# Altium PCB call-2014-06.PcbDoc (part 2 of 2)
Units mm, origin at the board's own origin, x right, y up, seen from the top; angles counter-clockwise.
Board outline 60 x 92 mm, 2 copper layers (Top Layer, Bottom Layer); 65 components, 45 nets, 265 pads, 33 vias.
Unrouted connection lines stored in the file: 4.
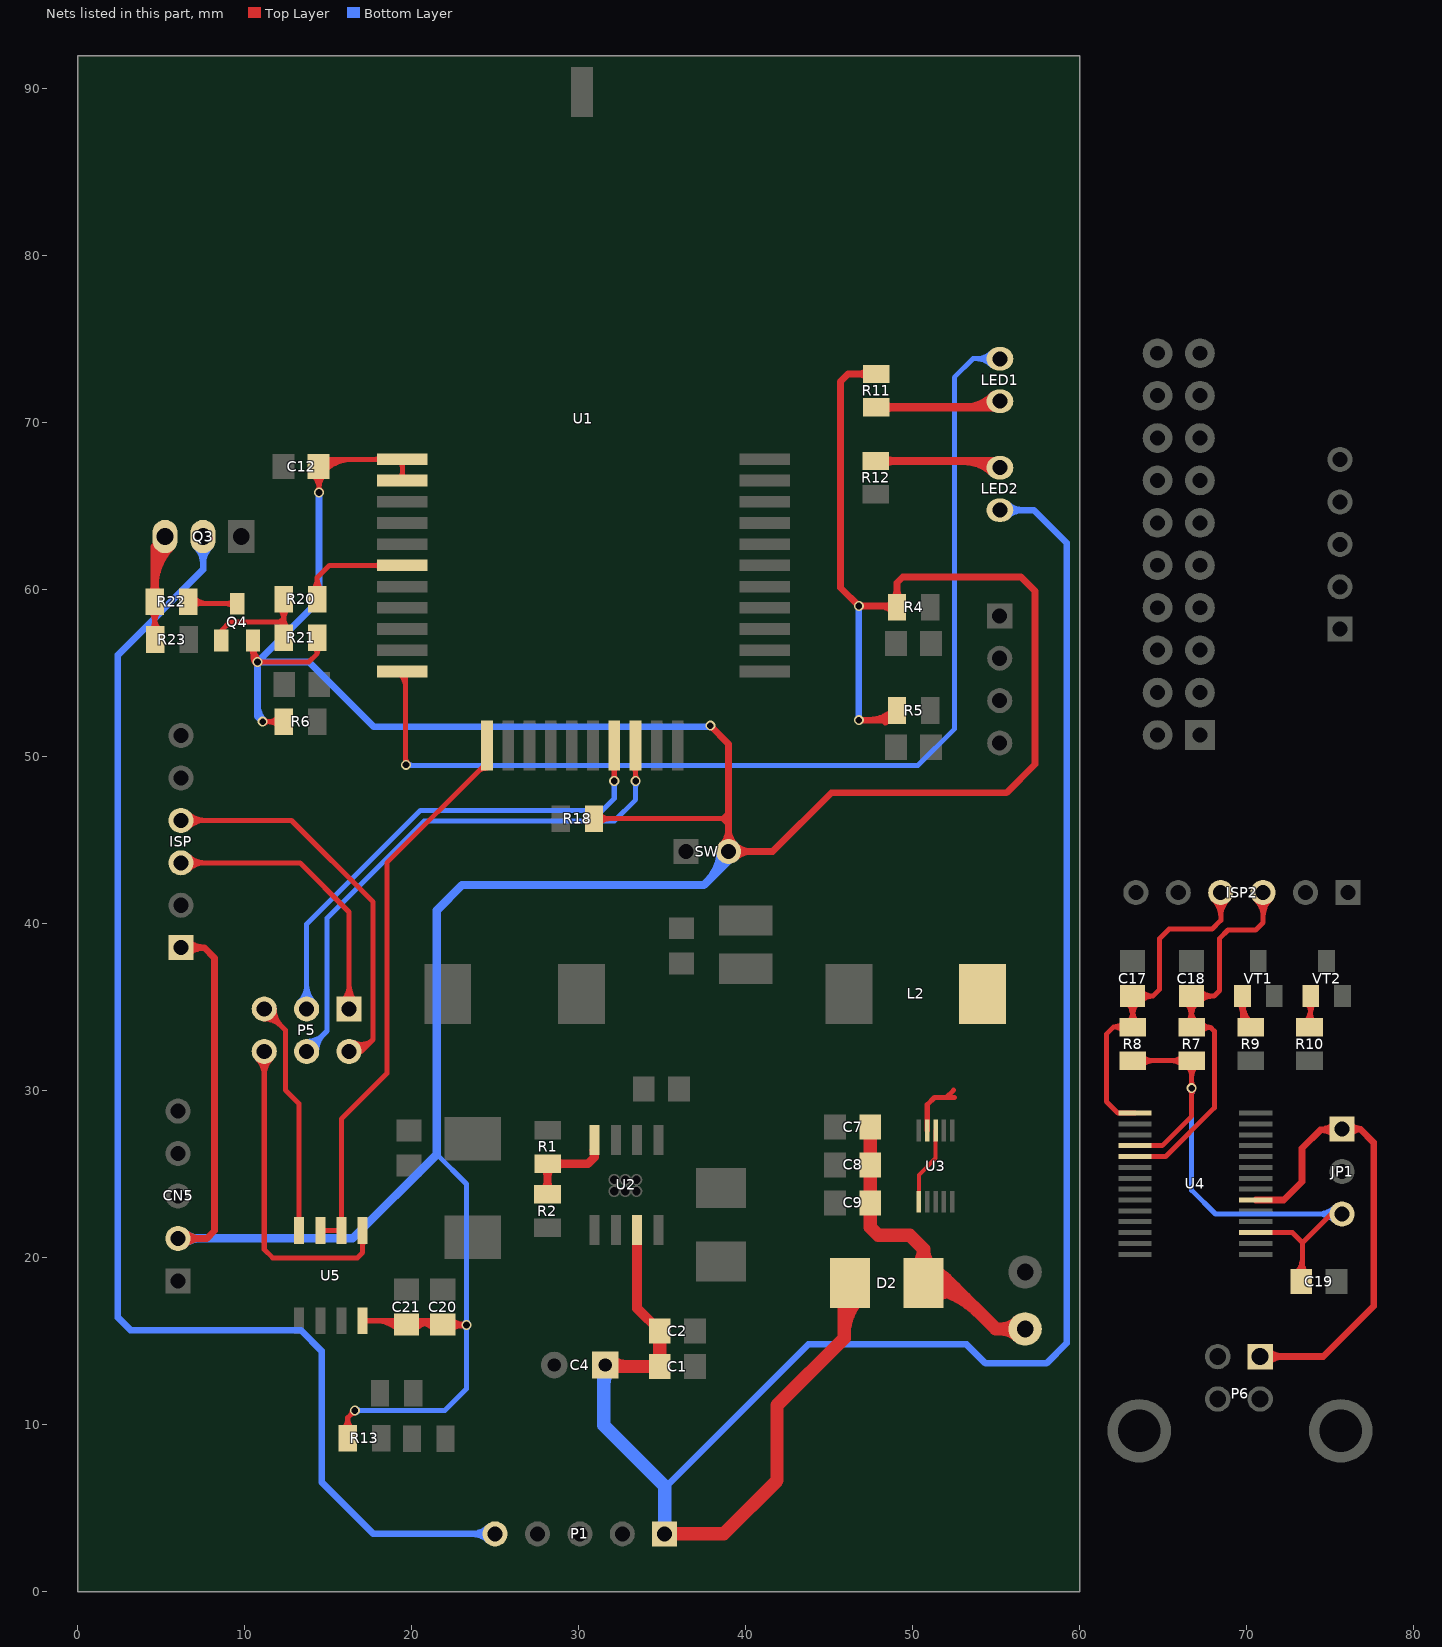
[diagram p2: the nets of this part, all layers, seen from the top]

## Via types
v1: diameter 0.6, hole 0.4, Top Layer to Bottom Layer, 33 vias

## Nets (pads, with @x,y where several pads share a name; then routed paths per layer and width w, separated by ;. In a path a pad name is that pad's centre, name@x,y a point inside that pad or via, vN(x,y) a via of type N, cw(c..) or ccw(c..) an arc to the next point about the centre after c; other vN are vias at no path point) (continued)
NetL2_1: L2.1 U3.9 | length 4
  Top Layer w0.3: U3.9@50.88,27.635 50.88,29.177 51.315,29.612 52.515,29.612 ; 52.024,29.614 52.459,30.049
NetLED1_1: LED1.1 R11.2 | length 11.4
  Top Layer w0.5: R11.2@47.82,70.93 54.86,70.93 LED1.1@55.23,71.3 ; R11.2@48.282,70.718 cw(c48.794,70.206) 48.794,70.93 cw(c48.794,71.654) R11.2@48.282,71.142 ; 53.15,70.93 ccw(c53.15,73.28) LED1.1@54.812,71.618 ; 54.357,70.93 ccw(c54.357,72.073) LED1.1@55.165,71.265
NetLED2_2: LED2.2 R12.2 | length 11.6
  Top Layer w0.5: R12.2@47.79,67.72 54.83,67.72 LED2.2@55.23,67.32 ; R12.2@48.252,67.508 cw(c48.764,66.996) 48.764,67.72 cw(c48.764,68.444) R12.2@48.252,67.932 ; 53.078,67.72 cw(c53.078,65.268) LED2.2@54.812,67.002 ; 54.285,67.72 cw(c54.285,66.475) LED2.2@55.165,67.355
NetQ3_3: Q3.3 R22.1 R23.2 | length 14.9
  Top Layer w0.3: R22.1@4.337,58.757 cw(c3.654,58.074) 4.62,58.074 cw(c5.586,58.074) R22.1@4.903,58.757 ; R23.2@4.367,57.563 ccw(c3.757,58.173) 4.62,58.173 ; 4.62,58.318 ccw(c5.688,58.318) R23.2@4.933,57.563 ; R22.1@4.62,59.29 4.62,57.06 R23.2@4.65,57.03
  Top Layer w0.5: R22.1@4.408,59.752 ccw(c3.896,60.264) 4.62,60.264 ccw(c5.344,60.264) R22.1@4.832,59.752 ; R22.1@4.62,59.29 4.62,62.579 Q3.3@5.24,63.199 ; 4.62,60.245 cw(c7.944,60.245) Q3.3@5.594,62.595 ; 4.62,61.452 cw(c6.737,61.452) Q3.3@5.24,62.949
NetQ4_1: Q4.1 R20.1 R21.1 | length 10
  Top Layer w0.3: Q4.1@8.611,56.975 8.611,57.552 9.134,58.075 12.126,58.075 12.351,58.3 ; R21.1@12.068,57.663 ccw(c11.385,58.346) 12.351,58.346 ccw(c13.317,58.346) R21.1@12.634,57.663 ; R20.1@12.068,58.917 cw(c11.385,58.234) 12.351,58.234 cw(c13.317,58.234) R20.1@12.634,58.917 ; R21.1@12.351,57.13 R20.1@12.351,59.45
NetQ4_3: Q4.3 R22.2 | length 5.5
  Top Layer w0.3: R22.2@6.62,59.29 6.735,59.175 Q4.3@9.561,59.175 ; R22.2@6.903,59.007 cw(c7.308,58.602) 7.308,59.175 ; R22.2@6.903,59.573 ccw(c7.863,60.533) 7.863,59.175 ; Q4.3@9.367,58.981 ccw(c8.897,58.511) 8.897,59.175 ccw(c8.897,59.839) Q4.3@9.367,59.369
NetR1_1: R1.1 R2.1 U2.4 | length 9.9
  Top Layer w0.5: R2.1@27.928,24.022 ccw(c27.416,24.534) 28.14,24.534 ccw(c28.864,24.534) R2.1@28.352,24.022 ; R1.1@27.938,25.438 cw(c27.45,24.95) 28.14,24.95 ; R2.1@28.14,23.81 R1.1@28.14,25.64 ; 28.14,24.902 cw(c28.898,24.902) R1.1@28.362,25.438 ; R1.1@28.15,25.65 R1.1@28.14,25.64 ; R1.1@28.612,25.438 cw(c29.1,24.95) 29.1,25.64 ; R1.1@28.612,25.862 ccw(c29.148,26.398) 29.148,25.64 ; 30.787,25.857 ccw(c30.385,26.259) U2.4@30.919,26.453 ; U2.4@30.966,27.07 30.966,26.036 30.57,25.64 R1.1@28.14,25.64
NetR9_1: R9.1 VT1.1 | length 5.8
  Top Layer w0.3: VT1.1@69.505,35.283 cw(c68.908,34.685) 69.753,34.685 cw(c70.598,34.685) VT1.1@70,35.283 ; 69.753,34.632 ccw(c70.816,34.632) R9.1@70.064,33.881 ; VT1.1@69.753,35.357 ccw(c71.54,35.357) R9.1@70.276,34.093 ; VT1.1@69.753,35.68 69.753,33.817 R9.1@70.03,33.54
NetR10_1: R10.1 VT2.1 | length 4.7
  Top Layer w0.3: R10.1@73.487,34.093 ccw(c72.635,34.945) 73.84,34.945 ; VT2.1@73.593,35.283 cw(c72.995,34.685) 73.84,34.685 cw(c74.685,34.685) VT2.1@74.087,35.283 ; 73.84,34.607 ccw(c74.567,34.607) R10.1@74.053,34.093 ; VT2.1@73.84,35.68 73.84,34.06 R10.1@74.01,33.89
NetR20_2: R20.2 U1.6 | length 9
  Top Layer w0.3: R20.2@14.068,59.983 ccw(c13.38,60.671) 14.353,60.671 ; R20.2@14.351,59.45 14.353,59.452 14.353,60.741 15.082,61.47 U1.6@19.446,61.47 ; 14.353,60.661 ccw(c15.312,60.661) R20.2@14.634,59.983 ; U1.6@18.155,61.329 ccw(c17.813,60.987) 17.813,61.47 ccw(c17.813,61.953) U1.6@18.155,61.611
PA1: LED1.2 U1.11 | length 67
  Top Layer w0.3: U1.11@19.305,54.979 cw(c18.5,54.174) 19.638,54.174 ; U1.11@19.446,55.12 19.638,54.928 v1@19.638,49.526 ; 19.638,49.97 ccw(c20.116,49.97) v1@19.778,49.632
  Bottom Layer w0.3: v1@19.718,49.495 50.33,49.495 52.499,51.664 52.499,72.729 53.622,73.852 LED1.2@54.899,73.852 ; v1@19.778,49.632 ccw(c20.109,49.963) 20.109,49.495 ; 53.773,73.852 cw(c53.773,72.483) LED1.2@54.741,73.451 ; 53.831,73.852 ccw(c53.831,75.139) LED1.2@54.741,74.229
  other v1: 19.672,49.526
RW: P1.5 Q3.2 | length 85.6
  Bottom Layer w0.4: Q3.2@7.131,62.56 cw(c6.192,61.621) 7.52,61.621 cw(c8.848,61.621) Q3.2@7.909,62.56 ; Q3.2@7.52,63.199 7.52,61.216 2.412,56.108 2.412,16.432 3.165,15.679 13.364,15.679 14.619,14.424 14.619,6.581 17.72,3.48 P1.5@25,3.48 ; P1.5@24.611,3.091 ccw(c23.672,2.152) 23.672,3.48 ccw(c23.672,4.808) P1.5@24.611,3.869
SHINENG: U1.12 U5.2 U5.3 | length 36.2
  Top Layer w0.3: U5.3@14.536,21.64 U5.2@15.806,21.64 15.806,28.326 18.52,31.04 18.52,43.658 24.518,49.656 U1.12@24.518,50.683 ; U5.3@14.642,21.534 cw(c14.898,21.278) 14.898,21.64 cw(c14.898,22.002) U5.3@14.642,21.746 ; U5.2@15.7,21.534 ccw(c15.444,21.278) 15.444,21.64 ccw(c15.444,22.002) U5.2@15.7,21.746 ; U5.2@15.7,22.246 ccw(c15.444,22.502) 15.806,22.502 ccw(c16.168,22.502) U5.2@15.912,22.246 ; 23.967,49.105 cw(c24.518,48.553) U1.12@24.518,49.333
UART_RXD: P5.5 U1.19 | length 37.3
  Top Layer w0.3: U1.19@33.267,49.392 cw(c32.9,49.025) 33.419,49.025 ; v1@33.312,48.665 ccw(c33.056,48.921) 33.419,48.921 ccw(c33.781,48.921) v1@33.525,48.665 ; U1.19@33.408,50.683 33.419,50.673 v1(33.419,48.559) ; 33.419,49.076 cw(c33.865,49.076) U1.19@33.549,49.392
  Bottom Layer w0.3: P5.5@13.72,32.37 14.941,33.591 14.941,40.349 20.753,46.161 32.142,46.161 33.419,47.437 v1(33.419,48.559) ; P5.5@13.72,32.97 ccw(c13.72,34.419) 14.744,33.394 ccw(c15.769,32.37) P5.5@14.32,32.37 ; v1@33.312,48.453 cw(c33.056,48.197) 33.419,48.197 cw(c33.781,48.197) v1@33.525,48.453
"UART_RXD 485": P5.6 U5.1 | length 22.3
  Top Layer w0.3: P5.6@10.756,31.946 cw(c9.731,30.921) 11.18,30.921 cw(c12.629,30.921) P5.6@11.604,31.946 ; P5.6@11.18,32.37 11.18,20.512 11.682,20.01 16.76,20.01 17.076,20.326 U5.1@17.076,21.64 ; U5.1@16.97,21.034 cw(c16.714,20.778) 17.076,20.778 cw(c17.438,20.778) U5.1@17.182,21.034
UART_RXD_USB: C18.2 ISP2.3 ISP.3 P5.1 R7.1 U4.5 | length 54.1
  Top Layer w0.3: ISP.3@6.19,43.66 13.32,43.66 16.26,40.72 P5.1@16.26,34.91 ; ISP.3@6.614,43.236 cw(c7.639,42.211) 7.639,43.66 cw(c7.639,45.109) ISP.3@6.614,44.084 ; P5.1@15.836,35.334 ccw(c14.811,36.359) 16.26,36.359 ccw(c17.709,36.359) P5.1@16.684,35.334 ; U4.5@63.32,26.07 65.155,26.07 68.07,28.985 68.07,33.58 67.84,33.81 ; C18.2@66.344,35.326 cw(c65.49,34.473) 66.697,34.473 cw(c67.904,34.473) C18.2@67.051,35.326 ; R7.1@66.434,34.093 ccw(c65.798,34.729) 66.697,34.729 ; 66.697,34.822 ccw(c67.729,34.822) R7.1@67,34.093 ; C18.2@67.151,35.326 cw(c68.004,34.473) 68.004,35.68 cw(c68.004,36.887) C18.2@67.151,36.034 ; R7.1@67.27,33.549 cw(c67.84,33.057) 67.84,33.81 ; R7.1@67.27,34.071 ccw(c67.84,34.563) 67.84,33.81 ; ISP2.3@70.566,41.456 cw(c69.541,40.431) 70.99,40.431 cw(c72.439,40.431) ISP2.3@71.414,41.456 ; ISP2.3@70.99,41.88 70.99,40.08 70.55,39.64 68.89,39.64 68.39,39.14 68.39,36.02 68.05,35.68 C18.2@66.697,35.68 66.697,33.829 R7.1@66.717,33.81 67.84,33.81
UART_TXD: P5.2 U1.18 | length 34
  Top Layer w0.3: U1.18@31.997,49.392 cw(c31.655,49.05) 32.138,49.05 cw(c32.621,49.05) U1.18@32.279,49.392 ; v1@32.032,48.665 ccw(c31.776,48.921) 32.138,48.921 ccw(c32.5,48.921) v1@32.244,48.665 ; v1(32.138,48.559) U1.18@32.138,50.683
  Bottom Layer w0.3: P5.2@13.296,35.334 ccw(c12.271,36.359) 13.72,36.359 ccw(c15.169,36.359) P5.2@14.144,35.334 ; P5.2@13.72,34.91 13.72,39.993 20.524,46.797 31.423,46.797 32.138,47.512 v1(32.138,48.559) ; v1@32.032,48.453 cw(c31.776,48.197) 32.138,48.197 cw(c32.5,48.197) v1@32.244,48.453
"UART_TXD 485": P5.3 U5.4 | length 17
  Top Layer w0.3: P5.3@11.18,34.31 cw(c11.18,32.861) 12.204,33.886 cw(c13.229,34.91) P5.3@11.78,34.91 ; P5.3@11.18,34.91 12.45,33.64 12.45,30.05 13.266,29.234 U5.4@13.266,21.64 ; U5.4@13.16,22.246 ccw(c12.904,22.502) 13.266,22.502 ccw(c13.628,22.502) U5.4@13.372,22.246
UART_TXD_USB: C17.2 ISP2.4 ISP.4 P5.4 R8.1 U4.1 | length 58.3
  Top Layer w0.3: ISP.4@6.19,46.2 12.81,46.2 17.7,41.31 17.7,33.08 ; ISP.4@6.614,45.776 cw(c7.639,44.751) 7.639,46.2 cw(c7.639,47.649) ISP.4@6.614,46.624 ; P5.4@15.99,32.35 16.97,32.35 17.7,33.08 ; P5.4@16.26,32.37 ccw(c16.601,33.023) 17.122,32.502 ; P5.4@16.399,32.636 ccw(c16.799,33.403) 17.411,32.791 ; P5.4@16.538,32.902 ccw(c16.998,33.782) 17.7,33.08 ; 62.047,33.84 ccw(c62.047,34.703) R8.1@62.657,34.093 ; R8.1@62.629,33.559 ccw(c62.04,33.083) 62.04,33.84 ; C17.2@62.826,35.326 cw(c61.973,34.473) 63.18,34.473 cw(c64.387,34.473) C17.2@63.534,35.326 ; R8.1@62.907,34.093 ccw(c62.248,34.752) 63.18,34.752 ; R8.1@63.18,33.82 C17.2@63.18,35.68 64.39,35.68 ; 63.18,34.8 ccw(c64.18,34.8) R8.1@63.473,34.093 ; R8.1@63.19,33.81 63.16,33.84 62.04,33.84 ; U4.1@63.32,28.67 62.3,28.67 61.6,29.37 61.6,33.4 62.04,33.84 ; C17.2@63.654,35.349 cw(c64.39,34.698) 64.39,35.68 ; C17.2@63.654,36.011 ccw(c64.39,36.662) 64.39,35.68 ; ISP2.4@68.026,41.456 cw(c66.977,40.407) 68.46,40.407 ; ISP2.4@68.45,41.88 68.46,41.87 68.46,40.22 67.93,39.69 65.36,39.69 64.8,39.13 64.8,36.09 64.39,35.68 ; 68.46,40.456 cw(c69.874,40.456) ISP2.4@68.874,41.456
VCC: JP1.1 P6.1 U4.20 | length 33.8
  Top Layer w0.4: U4.20@70.559,23.47 72.23,23.47 73.32,24.56 73.32,26.57 74.42,27.67 ; P6.1@70.815,14.095 74.595,14.095 77.61,17.11 77.61,26.92 76.82,27.71 ; P6.1@71.212,13.697 cw(c72.173,12.736) 72.173,14.095 cw(c72.173,15.453) P6.1@71.212,14.492 ; 74.489,27.67 cw(c74.489,26.479) JP1.1@75.331,27.321 ; JP1.1@75.306,28.072 cw(c74.42,28.847) 74.42,27.67 ; JP1.1@76.16,27.38 cw(c76.82,26.885) 76.82,27.71 ; JP1.1@76.16,28.04 ccw(c76.82,28.535) 76.82,27.71 ; 74.42,27.67 75.68,27.67 JP1.1@75.72,27.71 76.82,27.71
VCC_9V: C7.2 C8.2 C9.2 D2.1 pad.0@56.74,15.75 U3.1 U3.8 | length 42.9
  Top Layer w0.254: U3.1@50.38,23.36 50.38,24.973 51.38,25.973 U3.8@51.38,27.635
  Top Layer w0.8: C7.2@47.51,28.102 47.464,28.056 47.464,21.832 47.946,21.35 49.83,21.35 50.66,20.52 ; D2.1@50.121,18.781 cw(c51.029,17.785) 51.982,18.738 ; D2.1@50.142,19.4 ccw(c49.19,20.52) 50.66,20.52 ; D2.1@50.66,18.99 cw(c50.66,16.404) 52.488,18.233 ; D2.1@51.178,19.4 cw(c52.13,20.52) 50.66,20.52 ; D2.1@51.199,17.599 cw(c52.16,16.548) 53.166,17.555 ; D2.1@51.307,18.019 cw(c52.231,17.348) 52.231,18.49 ; D2.1@51.307,18.961 ccw(c52.231,19.632) 52.231,18.49 ; 52.574,18.147 ccw(c51.594,17.167) 50.66,18.19 cw(c50.66,13.673) 53.854,16.867 ; pad.0@56.316,15.326 ccw(c55.291,14.301) 55.291,15.75 ccw(c55.291,17.199) pad.0@56.316,16.174 ; pad.0@56.74,15.75 54.971,15.75 52.231,18.49 ; 50.66,20.52 D2.1@50.66,18.49 52.231,18.49
VCC_24V: C1.2 C2.2 C4.1 D2.2 LED2.1 P1.1 U2.7 | length 135.8
  Top Layer w0.6: U2.7@33.506,21.67 33.506,16.984 C2.2@34.87,15.62
  Top Layer w0.8: C4.1@31.594,13.59 31.684,13.5 C1.2@34.87,13.5 ; C4.1@31.877,13.873 ccw(c32.777,14.773) 32.777,13.5 ; C1.2@34.78,13.59 C1.2@34.87,13.5 ; C2.2@34.95,15.84 34.87,15.76 C1.2@34.87,13.5 ; P1.1@35.16,3.48 38.695,3.48 41.886,6.671 41.886,11.174 45.9,15.188 D2.2@45.9,18.45 ; P1.1@35.407,3.233 cw(c36.005,2.635) 36.005,3.48 cw(c36.005,4.325) P1.1@35.407,3.727 ; 45.9,15.39 cw(c49.06,15.39) D2.2@46.826,17.624
  Bottom Layer w0.4: 35.16,6.229 43.757,14.826 53.239,14.826 54.378,13.687 58.01,13.687 59.23,14.907 59.23,62.809 57.259,64.78 LED2.1@55.23,64.78 ; LED2.1@55.684,64.426 cw(c56.537,63.573) 56.537,64.78 cw(c56.537,65.987) LED2.1@55.684,65.134
  Bottom Layer w0.8: 31.519,12.443 cw(c32.741,12.443) C4.1@31.877,13.307 ; C4.1@31.594,13.59 31.519,13.515 31.519,9.975 35.16,6.334 ; P1.1@34.913,3.727 ccw(c34.315,4.325) 35.16,4.325 ccw(c36.005,4.325) P1.1@35.407,3.727 ; P1.1@35.16,3.48 35.16,6.229
VDD33: C12.2 C19.2 C20.2 C21.2 CN5.2 ISP.1 JP1.3 Q4.2 R4.2 R5.2 R6.2 R7.2 R8.2 R11.1 R13.2 R18.2 R21.2 SW.2 U1.1 U1.2 U4.4 U4.17 U5.8 | length 346.4
  Top Layer w0.3: Q4.2@10.317,56.556 cw(c9.879,56.118) 10.498,56.118 ; 10.498,55.991 ccw(c11.085,55.991) v1@10.67,55.576 ; 10.498,56.055 cw(c11.206,56.055) Q4.2@10.705,56.556 ; Q4.2@10.498,56.715 ccw(c11.809,56.715) 10.882,55.788 ccw(c11.138,56.044) 11.138,55.682 ccw(c11.138,55.32) v1@10.882,55.576 ; Q4.2@10.511,56.975 10.498,56.962 10.498,55.96 v1(10.776,55.682) 13.85,55.682 14.351,56.183 ; v1(11.087,52.116) R6.2@12.351,52.116 ; v1@11.193,52.01 cw(c11.449,51.754) 11.449,52.116 cw(c11.449,52.478) v1@11.193,52.222 ; R6.2@12.068,51.833 ccw(c11.385,51.15) 11.385,52.116 ccw(c11.385,53.082) R6.2@12.068,52.399 ; C12.2@14.08,66.927 cw(c13.159,66.006) v1@14.462,66.006 ; R21.2@14.149,56.535 cw(c13.944,56.183) 14.351,56.183 ; R21.2@14.351,57.13 14.351,56.183 ; v1@14.356,65.943 ccw(c14.1,66.199) 14.462,66.199 ccw(c14.824,66.199) v1@14.568,65.943 ; C12.2@14.363,67.552 cw(c15.011,66.904) C12.2@15.011,67.82 ; C12.2@14.434,67.381 C12.2@14.462,67.353 ; v1(14.462,65.837) C12.2@14.462,67.353 ; 14.462,66.141 cw(c15.574,66.141) C12.2@14.788,66.927 ; R21.2@14.553,56.535 ccw(c14.758,56.183) 14.351,56.183 ; C12.2@14.575,67.34 cw(c15.735,66.18) 15.735,67.82 ; C12.2@14.788,67.127 cw(c16.46,65.455) 16.46,67.82 ; R13.2@15.897,9.733 ccw(c15.214,10.416) 16.18,10.416 ccw(c17.146,10.416) R13.2@16.463,9.733 ; R13.2@16.18,9.2 16.18,10.439 v1(16.604,10.863) ; v1@16.454,10.863 cw(c16.092,10.863) 16.348,10.607 cw(c16.604,10.351) v1@16.604,10.713 ; U5.8@17.076,16.24 21.64,16.24 C20.2@21.87,16.01 ; U5.8@17.182,16.134 cw(c17.438,15.878) 17.438,16.24 cw(c17.438,16.602) U5.8@17.182,16.346 ; 17.828,16.24 cw(c17.828,14.248) C21.2@19.236,15.656 ; U1.1@18.155,67.679 ccw(c17.813,67.337) 17.813,67.82 ccw(c17.813,68.303) U1.1@18.155,67.961 ; 18.552,16.24 cw(c18.552,14.972) C21.2@19.449,15.869 ; 18.938,16.24 ccw(c18.938,16.662) C21.2@19.236,16.364 ; U1.2@19.305,66.691 ccw(c18.963,67.033) 19.446,67.033 ccw(c19.929,67.033) U1.2@19.587,66.691 ; U1.1@19.305,67.679 cw(c18.963,67.337) 19.446,67.337 cw(c19.929,67.337) U1.1@19.587,67.679 ; U1.2@19.446,66.55 U1.1@19.446,67.82 14.929,67.82 C12.2@14.462,67.353 ; C21.2@19.931,15.869 cw(c20.828,14.972) 20.828,16.24 ; C21.2@20.008,16.24 cw(c20.008,14.248) C20.2@21.416,15.656 ; C21.2@20.144,15.656 cw(c21.552,14.248) C20.2@21.552,16.24 ; C21.2@20.144,16.364 ccw(c20.442,16.662) 20.442,16.24 ; 20.732,16.24 cw(c20.732,14.972) C20.2@21.629,15.869 ; 21.118,16.24 ccw(c21.118,16.662) C20.2@21.416,16.364 ; R18.2@30.841,46.52 R18.2@31.138,46.817 ; R18.2@30.925,46.304 38.624,46.304 ; R18.2@31.208,46.021 cw(c31.891,45.338) 31.891,46.304 cw(c31.891,47.27) R18.2@31.208,46.587 ; 38.984,45.944 38.624,46.304 ; 38.984,46.664 38.624,46.304 ; R8.2@63.19,31.81 R7.2@66.717,31.81 66.717,28.487 64.95,26.72 U4.4@63.32,26.72 ; R8.2@63.723,31.527 cw(c64.406,30.844) 64.406,31.81 cw(c64.406,32.776) R8.2@63.723,32.093 ; R7.2@66.184,31.527 ccw(c65.501,30.844) 65.501,31.81 ccw(c65.501,32.776) R7.2@66.184,32.093 ; R7.2@66.434,31.527 cw(c65.751,30.844) 66.717,30.844 cw(c67.682,30.844) R7.2@67,31.527 ; v1@66.611,30.064 cw(c66.355,29.808) 66.717,29.808 cw(c67.079,29.808) v1@66.823,30.064 ; v1@66.611,30.276 ccw(c66.355,30.532) 66.717,30.532 ccw(c67.079,30.532) v1@66.823,30.276 ; U4.17@70.559,21.52 72.74,21.52 73.35,20.91 ; C19.2@72.926,19.034 ccw(c71.904,20.056) 73.35,20.056 ; C19.2@73.139,18.821 ccw(c72.628,19.332) 73.35,19.332 ; C19.2@73.28,18.58 73.35,18.65 73.35,20.91 ; 73.35,19.718 ccw(c74.318,19.718) C19.2@73.634,19.034 ; JP1.3@75.72,22.63 75.07,22.63 73.35,20.91
  Top Layer w0.4: CN5.2@6.02,21.17 7.742,21.17 8.201,21.629 8.201,37.964 7.585,38.58 ISP.1@6.19,38.58 ; CN5.2@6.409,20.781 cw(c7.348,19.842) 7.348,21.17 cw(c7.348,22.498) CN5.2@6.409,21.559 ; ISP.1@6.579,38.191 cw(c7.518,37.252) 7.518,38.58 cw(c7.518,39.908) ISP.1@6.579,38.969 ; C20.2@21.87,16.01 21.893,15.987 v1(23.289,15.987) ; C20.2@22.288,15.692 cw(c23.001,14.979) v1@23.001,15.987 ; C20.2@22.288,16.328 ccw(c23.112,17.152) v1@23.112,15.987 ; v1(37.893,51.871) 38.984,50.78 SW.2@38.984,44.335 41.62,44.335 45.135,47.85 55.617,47.85 57.327,49.56 57.327,59.936 56.489,60.774 49.417,60.774 49.07,60.427 R4.2@49.07,58.97 49.004,59.036 v1(46.787,59.036) 45.689,60.134 45.689,72.479 46.14,72.93 R11.1@47.82,72.93 ; SW.2@38.595,44.724 ccw(c37.656,45.663) 38.984,45.663 ccw(c40.312,45.663) 39.373,44.724 ccw(c40.312,45.663) 40.312,44.335 ccw(c40.312,43.007) SW.2@39.373,43.946 ; v1(46.787,52.2) 48.49,52.2 R5.2@49.07,52.78 ; R11.1@47.323,72.683 ccw(c46.725,72.085) 46.725,72.93 ccw(c46.725,73.775) R11.1@47.323,73.177 ; 47.428,52.2 ccw(c47.428,54.172) R5.2@48.823,52.777 ; 48.066,59.036 cw(c48.066,57.966) R4.2@48.823,58.723 ; 48.365,52.075 cw(c48.755,51.685) R5.2@48.948,52.202 ; 48.384,59.036 ccw(c48.384,59.656) R4.2@48.823,59.217 ; 48.394,52.2 ccw(c48.394,53.206) R5.2@49.105,52.495 ; R4.2@48.823,59.467 ccw(c48.225,60.065) 49.07,60.065 ccw(c49.915,60.065) R4.2@49.317,59.467
  Bottom Layer w0.3: v1(16.604,10.863) 21.99,10.863 23.289,12.162 23.289,24.427 21.508,26.208 ; v1@16.71,10.757 cw(c16.966,10.501) 16.966,10.863 cw(c16.966,11.225) v1@16.71,10.969 ; v1@23.183,15.881 cw(c22.927,15.625) 23.289,15.625 cw(c23.651,15.625) v1@23.395,15.881 ; v1@23.183,16.093 ccw(c22.927,16.349) 23.289,16.349 ccw(c23.651,16.349) v1@23.395,16.093 ; v1@66.611,30.064 cw(c66.355,29.808) 66.717,29.808 cw(c67.079,29.808) v1@66.823,30.064 ; v1(66.717,30.17) 66.717,24.053 68.14,22.63 JP1.3@75.72,22.63 ; JP1.3@75.296,22.206 ccw(c74.271,21.181) 74.271,22.63 ccw(c74.271,24.079) JP1.3@75.296,23.054
  Bottom Layer w0.4: 10.776,53.108 ccw(c12.079,53.108) v1@11.158,52.187 ; v1(11.087,52.116) 10.776,52.427 v1(10.776,55.682) ; v1(14.462,65.837) 14.462,59.368 v1(10.776,55.682) ; v1(37.893,51.871) 37.821,51.799 17.742,51.799 13.859,55.682 v1(10.776,55.682) ; v1(46.787,52.2) v1(46.787,59.036)
  Bottom Layer w0.5: CN5.2@6.02,21.17 16.47,21.17 21.508,26.208 21.508,40.813 23.024,42.329 37.501,42.329 38.984,43.812 SW.2@38.984,44.335 cw(c37.724,44.334) 38.615,43.443 ; CN5.2@6.374,20.816 cw(c7.227,19.963) 7.227,21.17 cw(c7.227,22.377) CN5.2@6.374,21.524 ; 37.763,42.591 ccw(c36.021,44.332) SW.2@38.484,44.335
pads on no net: JTAG.17 JTAG.19 P6.5 P6.6 U1. U1.3 U1.4 U1.5 U1.8 U1.9 U1.13 U1.16 U1.17 U1.21 U1.23 U1.24 U1.25 U1.26 U1.27 U1.28 U1.29 U2.2 U2.3 U2.5 U4.2 U4.3 U4.6 U4.8 U4.9 U4.10 U4.11 U4.12 U4.14 U4.19 U4.22 U4.24 U4.27 U4.28

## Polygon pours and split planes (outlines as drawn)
GND on Top Layer "Top Layer-No Net 1" (solid, remove dead copper, pour order 1000): 61.24,12.35 65.33,12.35 66.14,11.54 67.58,10.1 72.16,10.1 74.43,12.37 76.3,12.37 78.36,12.37 79.15,13.16 79.15,43.67 78.24,44.58 61.4,44.58 60.29,43.47 60.29,13.3 61.24,12.35
VCC_9V on Top Layer "Top Layer-No Net 1" (solid, remove dead copper, pour order 1001): 50.514,22.599 50.514,24.266 50.391,24.389 50.229,24.389 48.463,26.155 47.857,26.155 47.857,25.078 48.019,24.916 48.437,24.916 50.125,23.228 50.125,22.596 50.18,22.541 50.456,22.541
NetC3_2 on Top Layer "Top Layer-No Net 1" (solid, pour order 1002): 34.566,20.31 35.74,20.31 35.85,20.42 35.85,22.03 36.77,22.95 39.784,22.95 40.042,23.208 40.042,32.923 38.515,34.45 34.29,34.45 33.37,35.37 33.37,40.86 33.06,41.17 28.22,41.17 27.94,40.89 27.94,31.54 28.27,31.21 35.72,31.21 35.92,31.01 35.92,24.02 34.462,22.562 34.462,20.414
GND on Top Layer "Top Layer-No Net 1" (solid, pour order 1003): 50.514,26.859 50.514,29.491 49.187,30.818 44.005,30.818 42.944,31.879 42.944,36.853 41.575,38.222 35.095,38.222 34.797,37.924 34.797,35.759 35.095,35.461 39.366,35.461 40.961,33.866 40.961,30.959 42.764,29.156 48.412,29.156 48.773,28.795 48.773,26.871 48.939,26.705 50.36,26.705
NetC5_1 on Top Layer "Top Layer-No Net 1" (solid, pour order 1004): 43.551,32.259 43.551,38.093 42.412,39.232 35.01,39.232 34.744,39.498 34.744,41.433 34.934,41.623 47.423,41.623 48.277,40.769 48.277,32.236 47.659,31.618 44.192,31.618
NetL2_1 on Top Layer "Top Layer-No Net 1" (solid, pour order 1005): 52.424,41.554 56.302,41.554 56.646,41.21 56.646,29.702 56.411,29.467 52.25,29.467 52.053,29.664 52.053,41.183
GND on Top Layer "Top Layer-No Net 1" (solid, pour order 1006): 51.745,28.434 51.745,25.799 50.745,24.799 50.745,22.644 50.919,22.47 51.964,22.47 52.013,22.519 52.013,24.72 52.572,25.279 52.572,28.44 52.53,28.482 51.793,28.482
GND on Top Layer "Top Layer-No Net 1" (solid, pour order 1007): 51.802,22.741 54.035,20.508 58.171,20.508 58.471,20.208 58.471,18.249 58.195,17.973 55.037,17.973 50.745,22.265 50.745,22.75
NetC5_1 on Top Layer "Top Layer-No Net 1" (solid, pour order 1008): 25.385,40.751 25.385,41.344 26.01,41.969 34.208,41.969 34.744,41.433 35.259,40.918 36.284,40.918 38.37,40.918 38.464,41.012 38.417,41.059 38.417,41.499 37.915,41.499 37.586,41.828 37.586,45.382 37.285,45.683 35.026,45.683 34.647,45.304 33.755,44.412 31.439,44.412 20.317,44.412 19.558,43.653 19.293,43.388 19.293,40.751
GND on Top Layer "Top Layer-No Net 1" (solid, pour order 1009): 34.671,25.489 34.671,23.32 34.495,23.144 32.945,23.144 32.724,22.923 32.724,18.275 31.89,17.441 18.923,17.441 18.588,17.776 18.588,25.89 18.933,26.235 20.475,26.235 20.566,26.144 20.566,23.849 21.888,22.527 29.082,22.527 29.523,22.968 29.523,24.796 29.847,25.12 30.833,25.12 31.403,25.69 34.47,25.69
NetC5_1 on Top Layer "Top Layer-No Net 1" (solid, pour order 1010): 25.022,41.114 19.656,41.114 19.293,40.751 19.293,30.947 18.506,30.16 18.506,27.392 18.92,26.978 21.263,26.978 21.452,26.789 21.452,25.933 21.708,25.677 25.602,25.677 25.944,26.019 25.944,26.719 26.314,27.089 29.057,27.089 29.302,27.334 29.302,30.106 28.904,30.504 25.723,30.504 25.393,30.834 25.393,40.743
GND on Top Layer "Top Layer-No Net 1" (solid, remove dead copper, pour order 1011): 34.109,1.357 36.117,1.357 36.632,1.872 41.528,6.768 41.528,9.718 41.528,11.13 44.635,14.237 45.199,14.801 45.199,19.886 44.101,20.984 40.461,20.984 32.741,20.984 30.827,19.07 30.691,18.934 24.609,18.934 20.416,18.934 18.923,17.441 18.923,14.051 20.109,14.051 21.06,13.1 21.469,12.691 21.469,8.402 21.469,5.616 25.713,1.372 34.124,1.372 34.226,1.474
GND on Bottom Layer "Top Layer-No Net 1" (solid, pour order 1012): 60.81,0.61 78.64,0.61 79.11,1.08 79.11,43.71 78.2,44.62 61.45,44.62 60.65,43.82 60.65,0.77
GND on Bottom Layer "Top Layer-No Net 1" (solid, remove dead copper, pour order 1013): 12.425,0.192 48.113,0.192 48.799,0.878 48.799,4.137 55.764,11.102 58.679,11.102 59.237,11.66 59.237,75.952 57.939,77.25 42.311,77.25 40.951,75.89 40.951,52.885 39.57,51.504 20.136,51.504 19.339,52.301 19.339,75.319 17.519,77.139 2.003,77.139 0.386,75.522 0.386,11.862 1.073,11.175 4.158,11.175 11.187,4.146 11.187,1.43

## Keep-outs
Keep-Out Layer:
  circle w0.254: c10,11 r1.7
  circle w0.254: c10,81 r1.7
  circle w0.254: c50,81 r1.7
  circle w0.254: c50,11 r1.7
  lines w0.254: 1.199,10.981 cw(c1.199,12.18) 0,12.18 0,79.913 cw(c1.072,79.913) 1.072,80.985 4.045,80.985 11,87.94 11,90.73 ; 1.199,10.995 4.085,10.995 11,4.08 11,1.016 ccw(c12.016,1.016) 12.016,0 13,0 47,0 47.73,0 ccw(c47.73,1.27) 49,1.27 49,4.07 55.93,11 58.801,11 ccw(c58.801,12.199) 60,12.199 60,13 60,79.35 ; 11,90.678 11,90.73 ; 12.27,92 ccw(c12.27,90.73) 11,90.73 ; 13.28,92 14.01,92 48.01,92 ; 47.805,92 cw(c47.805,90.805) 49,90.805 49,87.93 55.93,81 58.928,81 cw(c58.928,79.928) 60,79.928 ; 60,45.31 79.4,45.31 79.45,45.26 ; 60.01,79.22 cw(c60.73,79.22) 60.73,79.94 61.61,79.94 78.28,79.94 78.85,79.94 cw(c78.85,79.34) 79.45,79.34 79.45,0.6 cw(c78.82,0.6) 78.82,-0.03 77.92,-0.03 61.72,-0.03 60.62,-0.03 ; 60.01,79.94 60.01,0.6 ccw(c60.62,0.6) 60.62,-0.01

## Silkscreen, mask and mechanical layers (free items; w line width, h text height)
Top Overlay:
  circle w0.254: c10,11 r3
  circle w0.254: c50,11 r3
  circle w0.254: c50,81 r3
  circle w0.254: c10,81 r3
  lines w0.254: 21.317,29.244 22.137,29.244 ; 21.737,28.854 21.737,29.674 ; 37.072,41.233 37.892,41.233 ; 37.492,40.843 37.492,41.663 ; 52.45,63.57 53.27,63.57 ; 52.56,70.44 53.38,70.44 ; 52.87,63.18 52.87,64 ; 52.98,70.02 52.98,70.84
  text "KEY2" at 58.52,57.58 h0.8 r90
  text "KEY3" at 58.54,52.04 h0.8 r90
  text "3.3V" at 38.219,46.875 h0.8
  text "+5V" at 73.16,27.07 h0.8 r90
  text "+3.3V" at 73.21,20.27 h0.8 r90
  text "GND" at 24.14,18.14 h0.8
  text "RW" at 25.2,6.04 h0.8 r90
  text "485_B" at 27.84,5.97 h0.8 r90
  text "GND" at 32.15,5.967 h0.8
  text "+24V" at 35.05,5.967 h0.8
  text "485_A" at 30.3,5.89 h0.8 r90

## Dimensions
14.01,92 to 13,0 on Keep-Out Layer
0,12.18 to 79.45,0.6 on Keep-Out Layer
